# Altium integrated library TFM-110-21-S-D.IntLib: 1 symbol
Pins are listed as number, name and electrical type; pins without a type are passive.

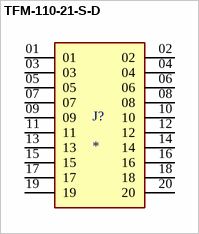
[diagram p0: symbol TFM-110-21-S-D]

## TFM-110-21-S-D
designator J?
TFM - Samtec 1.27mm Tiger Eyeâ„¢ ¦ High-Reliability Through Hole Header; MP: TFM-110-21-S-D
footprint SAMTEC_TFM-110-21-S-D
pins: 01, 02, 03, 04, 05, 06, 07, 08, 09, 10, 11, 12, 13, 14, 15, 16, 17, 18, 19, 20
